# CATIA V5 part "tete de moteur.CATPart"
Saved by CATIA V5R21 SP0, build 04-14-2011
Part number: tete de moteur
Material "Aluminium": density 2710 kg/m3, Young's modulus 7e+10 Pa, Poisson ratio 0.346, thermal expansion 2.36e-05 1/K
Bounding box of the stored display mesh (mm): x -16.989 to 17.003, y -17.05 to 17.05, z 0 to 13.5
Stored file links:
  C:\Users\Utilisateur\Desktop\Fichiers à télécharger dans l'ouvrage\Exercice 9 Pompe de ventilation.CATDrawing (corrigé)\tete de moteur.CATPart
  C:\Users\Olivier\Desktop\redaction TBM CATIA\pompe à moteur de ventilation refait\engine block.CATPart
  C:\Program Files\Dassault Systemes\B21\win_b64\startup\materials\French\Catalog.CATMaterial
  C:\Program Files\Dassault Systemes\B21\win_b64\resources\graphic\figures\CATIA_EnvironmentMap_Hall_512x512.jpg
  C:\Users\Utilisateur\Desktop\Fichiers à télécharger dans l'ouvrage\Exercice 9 Pompe de ventilation.CATDrawing (corrigé)\CATIA_EnvironmentMap_DSBlack_512x512.jpg
  C:\Program Files\Dassault Systemes\B21\win_b64\resources\graphic\figures\CATIA_EnvironmentMap_GridSpot_512x512.jpg
  C:\Program Files\Dassault Systemes\B21\win_b64\resources\graphic\figures\CATIA_EnvironmentMap_NonLinear_512x512.jpg
  C:\Program Files\Dassault Systemes\B21\win_b64\resources\graphic\figures\CATIA_EnvironmentMap_Square2_512x512.jpg
  C:\Users\Olivier\Desktop\redaction CATIA (local)\pompe à moteur de ventilation refait\Pompe_a_moteur_de_ventilation.CATProduct
  C:\Users\Olivier\Desktop\redaction CATIA (local)\pompe à moteur de ventilation refait\Ecrou a collerette M5.CATPart
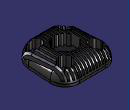
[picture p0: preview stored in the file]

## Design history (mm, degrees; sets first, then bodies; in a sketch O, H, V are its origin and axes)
Body1 (main body), material "Aluminium"
  Sketch1 on xy-plane, origin (0, 0, 0), H (1, 0, 0), V (0, 1, 0)
    point P1 (0, 0)
    point P2 (0, 1.25)
    point P3 (0, -12.5)
    arc A1 centre (-8.2069, 8.2501) radius 8.7999 from (-8.2068, 17.05) to (-16.9887, 7.686) ccw
    line L1 (-16.9887, 7.686) -> (-16.0612, -6.755)
    arc A2 centre (-5.0839, -6.0501) radius 10.9999 from (-16.0612, -6.755) to (-5.0838, -17.05) ccw
    line L2 (-5.0838, -17.05) -> (5.0898, -17.05)
    arc A3 centre (5.0899, -6.0501) radius 10.9999 from (5.0898, -17.05) to (16.0668, -6.7614) ccw
    line L3 (16.0668, -6.7614) -> (17.0027, 7.6809)
    arc A4 centre (8.2212, 8.2501) radius 8.7999 from (17.0027, 7.6809) to (8.2211, 17.05) ccw
    line L4 (8.2211, 17.05) -> (-8.2068, 17.05)
    distance L4 L2 = 34.1
    distance L4 H = 17.05
  Pad1: profile Sketch1, direction (0, 0, 1), length 13.5
  Fillet1: radius 8, on edge [face of Pad1 from Sketch1.L1 | end face of Pad1]
  Sketch2 on zx-plane, origin (0, 0, 0), H (-1, 0, 0), V (0, 0, 1)
    line L1 (0.5, 15.593) -> (0.5, 6.7271)
    point P1 (0.5, 6.7271)
    point P2 (1.5, 6.7271)
    line L2 (1.5, 15.593) -> (1.5, 6.7271)
    line L3 (0.5, 6.7271) -> (1.5, 6.7271)
    line L4 (0.5, 15.593) -> (1.5, 15.593)
    point P5 (1.5, 15.593)
    point P6 (0.5, 15.593)
    point P7 (2.5, 6.7271)
    point P8 (3.5, 6.7271)
    point P9 (3.5, 15.593)
    point P10 (2.5, 15.593)
    line L5 (2.5, 15.593) -> (2.5, 6.7271)
    line L6 (3.5, 15.593) -> (3.5, 6.7271)
    line L7 (2.5, 6.7271) -> (3.5, 6.7271)
    line L8 (2.5, 15.593) -> (3.5, 15.593)
    point P11 (4.5, 6.7271)
    point P12 (5.5, 6.7271)
    point P13 (5.5, 15.593)
    point P14 (4.5, 15.593)
    line L9 (4.5, 15.593) -> (4.5, 6.7271)
    line L10 (5.5, 15.593) -> (5.5, 6.7271)
    line L11 (4.5, 6.7271) -> (5.5, 6.7271)
    line L12 (4.5, 15.593) -> (5.5, 15.593)
    point P15 (6.5, 6.7271)
    point P16 (7.5, 6.7271)
    point P17 (7.5, 15.593)
    point P18 (6.5, 15.593)
    line L13 (6.5, 15.593) -> (6.5, 6.7271)
    line L14 (7.5, 15.593) -> (7.5, 6.7271)
    line L15 (6.5, 6.7271) -> (7.5, 6.7271)
    line L16 (6.5, 15.593) -> (7.5, 15.593)
    point P19 (8.5, 6.7271)
    point P20 (9.5, 6.7271)
    point P21 (9.5, 15.593)
    point P22 (8.5, 15.593)
    line L17 (8.5, 15.593) -> (8.5, 6.7271)
    line L18 (9.5, 15.593) -> (9.5, 6.7271)
    line L19 (8.5, 6.7271) -> (9.5, 6.7271)
    line L20 (8.5, 15.593) -> (9.5, 15.593)
    point P23 (10.5, 6.7271)
    point P24 (11.5, 6.7271)
    point P25 (11.5, 15.593)
    point P26 (10.5, 15.593)
    line L21 (10.5, 15.593) -> (10.5, 6.7271)
    line L22 (11.5, 15.593) -> (11.5, 6.7271)
    line L23 (10.5, 6.7271) -> (11.5, 6.7271)
    line L24 (10.5, 15.593) -> (11.5, 15.593)
    point P27 (12.5, 6.7271)
    point P28 (13.5, 6.7271)
    point P29 (13.5, 15.593)
    point P30 (12.5, 15.593)
    line L25 (12.5, 15.593) -> (12.5, 6.7271)
    line L26 (13.5, 15.593) -> (13.5, 6.7271)
    line L27 (12.5, 6.7271) -> (13.5, 6.7271)
    line L28 (12.5, 15.593) -> (13.5, 15.593)
    point P31 (14.5, 6.7271)
    point P32 (15.5, 6.7271)
    point P33 (15.5, 15.593)
    point P34 (14.5, 15.593)
    line L29 (14.5, 15.593) -> (14.5, 6.7271)
    line L30 (15.5, 15.593) -> (15.5, 6.7271)
    line L31 (14.5, 6.7271) -> (15.5, 6.7271)
    line L32 (14.5, 15.593) -> (15.5, 15.593)
    point P35 (-0.5, 6.7271)
    point P36 (-1.5, 6.7271)
    point P37 (-1.5, 15.593)
    point P38 (-0.5, 15.593)
    point P39 (-2.5, 6.7271)
    point P40 (-3.5, 6.7271)
    point P41 (-3.5, 15.593)
    point P42 (-2.5, 15.593)
    point P43 (-4.5, 6.7271)
    point P44 (-5.5, 6.7271)
    point P45 (-5.5, 15.593)
    point P46 (-4.5, 15.593)
    point P47 (-6.5, 6.7271)
    point P48 (-7.5, 6.7271)
    point P49 (-7.5, 15.593)
    point P50 (-6.5, 15.593)
    point P51 (-8.5, 6.7271)
    point P52 (-9.5, 6.7271)
    point P53 (-9.5, 15.593)
    point P54 (-8.5, 15.593)
    point P55 (-10.5, 6.7271)
    point P56 (-11.5, 6.7271)
    point P57 (-11.5, 15.593)
    point P58 (-10.5, 15.593)
    point P59 (-12.5, 6.7271)
    point P60 (-13.5, 6.7271)
    point P61 (-13.5, 15.593)
    point P62 (-12.5, 15.593)
    point P63 (-14.5, 6.7271)
    point P64 (-15.5, 6.7271)
    point P65 (-15.5, 15.593)
    point P66 (-14.5, 15.593)
    line L33 (-0.5, 15.593) -> (-0.5, 6.7271)
    line L34 (-1.5, 15.593) -> (-1.5, 6.7271)
    line L35 (-0.5, 6.7271) -> (-1.5, 6.7271)
    line L36 (-0.5, 15.593) -> (-1.5, 15.593)
    line L37 (-2.5, 15.593) -> (-2.5, 6.7271)
    line L38 (-3.5, 15.593) -> (-3.5, 6.7271)
    line L39 (-2.5, 6.7271) -> (-3.5, 6.7271)
    line L40 (-2.5, 15.593) -> (-3.5, 15.593)
    line L41 (-4.5, 15.593) -> (-4.5, 6.7271)
    line L42 (-5.5, 15.593) -> (-5.5, 6.7271)
    line L43 (-4.5, 6.7271) -> (-5.5, 6.7271)
    line L44 (-4.5, 15.593) -> (-5.5, 15.593)
    line L45 (-6.5, 15.593) -> (-6.5, 6.7271)
    line L46 (-7.5, 15.593) -> (-7.5, 6.7271)
    line L47 (-6.5, 6.7271) -> (-7.5, 6.7271)
    line L48 (-6.5, 15.593) -> (-7.5, 15.593)
    line L49 (-8.5, 15.593) -> (-8.5, 6.7271)
    line L50 (-9.5, 15.593) -> (-9.5, 6.7271)
    line L51 (-8.5, 6.7271) -> (-9.5, 6.7271)
    line L52 (-8.5, 15.593) -> (-9.5, 15.593)
    line L53 (-10.5, 15.593) -> (-10.5, 6.7271)
    line L54 (-11.5, 15.593) -> (-11.5, 6.7271)
    line L55 (-10.5, 6.7271) -> (-11.5, 6.7271)
    line L56 (-10.5, 15.593) -> (-11.5, 15.593)
    line L57 (-12.5, 15.593) -> (-12.5, 6.7271)
    line L58 (-13.5, 15.593) -> (-13.5, 6.7271)
    line L59 (-12.5, 6.7271) -> (-13.5, 6.7271)
    line L60 (-12.5, 15.593) -> (-13.5, 15.593)
    line L61 (-14.5, 15.593) -> (-14.5, 6.7271)
    line L62 (-15.5, 15.593) -> (-15.5, 6.7271)
    line L63 (-14.5, 6.7271) -> (-15.5, 6.7271)
    line L64 (-14.5, 15.593) -> (-15.5, 15.593)
    distance L2 L1 = 1
    distance L1 V = 0.5
    vertical: L1 V
    horizontal: L3 H, L4 H
    symmetry: P1 P35 V, P2 P36 V, P5 P37 V, P6 P38 V, P7 P39 V, P8 P40 V, P9 P41 V, P10 P42 V, P11 P43 V, P12 P44 V, P13 P45 V, P14 P46 V, P15 P47 V, P16 P48 V, P17 P49 V, P18 P50 V, P19 P51 V, P20 P52 V, P21 P53 V, P22 P54 V, P23 P55 V, P24 P56 V, P25 P57 V, P26 P58 V, P27 P59 V, P28 P60 V, P29 P61 V, P30 P62 V, P31 P63 V, P32 P64 V, P33 P65 V, P34 P66 V, L1 L33 V, L2 L34 V, L3 L35 V, L4 L36 V, L5 L37 V, L6 L38 V, L7 L39 V, L8 L40 V, L9 L41 V, L10 L42 V, L11 L43 V, L12 L44 V, L13 L45 V, L14 L46 V, L15 L47 V, L16 L48 V, L17 L49 V, L18 L50 V, L19 L51 V, L20 L52 V, L21 L53 V, L22 L54 V, L23 L55 V, L24 L56 V, L25 L57 V, L26 L58 V, L27 L59 V, L28 L60 V, L29 L61 V, L30 L62 V, L31 L63 V, L32 L64 V
  Pocket1: profile Sketch2, direction (0, -1, 0), length 18.5, mirrored extent
  Sketch3 on start face of Pad1, origin (0, 0, 0), H (1, 0, 0), V (0, -1, 0)
    circle A1 centre (0, 0) radius 6.5
    circle A2 centre (0, 0) radius 3
    arc A3 centre (-7.3863, -7.4252) radius 7.9198 from (-15.2898, -6.9174) to (-7.3861, -15.345) ccw
    line L1 (-15.2898, -6.9174) -> (-14.4551, 6.0795)
    arc A4 centre (-4.5756, 5.4452) radius 9.8998 from (-4.5754, 15.345) to (-14.4551, 6.0795) ccw
    line L2 (-4.5754, 15.345) -> (4.5808, 15.345)
    arc A5 centre (4.581, 5.4452) radius 9.8998 from (14.4601, 6.0852) to (4.5808, 15.345) ccw
    line L3 (14.4601, 6.0852) -> (15.3024, -6.9128)
    arc A6 centre (7.3992, -7.4252) radius 7.9198 from (7.399, -15.345) to (15.3024, -6.9128) ccw
    line L4 (7.399, -15.345) -> (-7.3861, -15.345)
    circle A7 centre (0, 0) radius 10.5
  MultiPocket1: profile Sketch3, domains (length 3.5; length 0; length 4; length 14; length 3.5)
  Sketch4 on face of Pocket1 from Sketch2.L27, origin (0, 0, 6.7271), H (1, 0, 0), V (0, 1, 0)
    circle A1 centre (9.545, 9.545) radius 1.5
    point P1 (9.545, 9.545)
    point P2 (-9.545, 9.545)
    distance P1 V = 9.545
    distance P1 H = 9.545
    radius A1 = 1.5
  Sketch5 on face of Pocket1, origin (0, 0, 6.7271), H (1, 0, 0), V (0, 1, 0)
    circle A1 centre (0, 0) radius 7
    radius A1 = 7
  Pocket2: profile Sketch5, direction (0, 0, -1), length 0, opposite side through (limit type 3)
  Sketch6 on face of Pocket2, origin (0, 0, 6.7271), H (1, 0, 0), V (0, 1, 0)
    circle A1 centre (9.545, 9.545) radius 4
    point P1 (9.545, 9.545)
    reference projected circle E1 centre (9.545, 9.545) radius 1.5 from Sketch4.A1
    radius A1 = 4
    concentricity: P1 E1
  Pocket3: profile Sketch6, direction (0, 0, 1), through (limit type 3)
  Pocket4: profile Sketch4, direction (0, 0, -1), through (limit type 3)
  RectPattern1: of Pocket3, Pocket4, Sketch4, direction 1 instances 2, spacing 19.09, along X axis reversed, direction 2 instances 2, spacing 19.09, along Y axis reversed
